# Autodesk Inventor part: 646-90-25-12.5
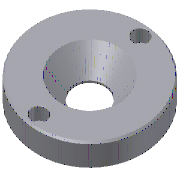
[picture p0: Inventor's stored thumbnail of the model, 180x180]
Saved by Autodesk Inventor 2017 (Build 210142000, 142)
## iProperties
IsCustomPart: 1
Created: 2016-02
Part Number: 646-90-25-12.5
Material: ANFOR XC 38 TS
Description: Locating Ring
Document SubType Name: Modeling
Designer: Sandeep
Standard Revision: 1
Manufacturer: RABOURDIN
Language: en-US
Size Designation: 646-90-25-12.5
Categories: <MemberInstance><Categories><Category DisplayName="Mold" InternalName="349578f2-f4d4-4954-8c09-8e99297a61c0" Mnemonic="MOLD"><Category DisplayName="Locatings" I
Density: 7.845 g/cm^3
Appearance: Default
Author: Sandeep
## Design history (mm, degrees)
sketch "Sketch1"
  geometry: L1 (0, -2.5)-(0, 15) reference; L2 (24, 12.5)-(12.5, 1); L3 (12.5, 1)-(12.5, 0); L4 (12.5, 0)-(45, 0); L5 (45, 0)-(45, 12.5); L6 (45, 12.5)-(24, 12.5); 1 further point
  constraints: 10 end point, 2 horizontal, 2 vertical, 1 point on line
  dimensions: "d0" = 45 deg angle of L1 L2; "d1" = 25 diameter of L3 L1 (= D2); "d2" = 90 diameter of L5 L1 (= D1); "d3" = 12.5 distance between parallel lines of L4 L6 (= A_); "d4" = 1 distance from line of L2.end L4 (= C_)
revolve "Revolution1" sketch "Sketch1" stored, may be unused: angle "d5" = 90 deg
sketch "Sketch2"
  geometry: 3 further points
  constraints: 2 vertical alignment
  dimensions: "d29" = 37 distance of point (0, 0) point (0, 37); "d30" = 37 distance of point (0, -37) point (0, 0)
hole "Hole1" sketch "Sketch2" diameter "d7" = 7; stored, may be unused: countersink angle "d11" = 90 deg, drill point angle "d13" = 0 deg; dims "d8" = 6, "d9" = 11, "d10" = 7, "d12" = 12.5 (= A_)
hole "Hole2" sketch "Sketch2" diameter "d31" = 7; stored, may be unused: countersink angle "d35" = 90 deg, drill point angle "d37" = 0 deg; dims "d32" = 6, "d33" = 11, "d34" = 7, "d36" = 12.5 (= A_)
chamfer "Chamfer1" distance "d14" = 1; stored, may be unused: second distance "d15" = 2, angle "d16" = 45 deg
chamfer "Chamfer2" distance "d17" = 0.5; stored, may be unused: second distance "d18" = 2, angle "d19" = 45 deg
chamfer "Chamfer3" distance "d20" = 0.3; stored, may be unused: second distance "d21" = 2, angle "d22" = 45 deg
sketch "Sketch3"
  geometry: L1 (0, -2.5)-(0, 15) reference; L2 (0, 0)-(45, 0); L3 (45, 0)-(45, 12.5); L4 (45, 12.5)-(0, 12.5); L5 (0, 12.5)-(0, 0)
  constraints: 8 end point, 2 parallel, 1 horizontal, 1 perpendicular
  dimensions: "d23" = 90 diameter of L3 L1 (= D1_CS); "d24" = 12.5 distance between parallel lines of L2 L4 (= A_CS)
feature "RevolutionSrf1" sketch "Sketch3" dims angle "d25" = 90 deg
body "Solid1"
body "Srf1"
other parameters: "D1" = 90 [user parameter; used in 1 equation term], "D2" = 25 [user parameter; used in 1 equation term], "A_" = 12.5 [user parameter; used in 3 equation terms], "C_" = 1 [user parameter; used in 1 equation term], "D1_CS" = 90 [user parameter; used in 1 equation term], "A_CS" = 12.5 [user parameter; used in 1 equation term], "d26" = 0, "d27" = 0, "d28" = 0
